// Mitsubishi GX Works2 project: MOD_SLAVE_v1   PLC: FX3G

// task Task_01 (event TRUE, interval 0, priority 31): POU_01

PROGRAM POU_01
VAR
  MODBUS_FB_SLAVE_1 : MODBUS_FB_SLAVE;
END_VAR
(* structured ladder/FBD written out as ST: instructions are called as NAME(EN, inputs, outputs); _pN, _eN, _tN stand for wires *)
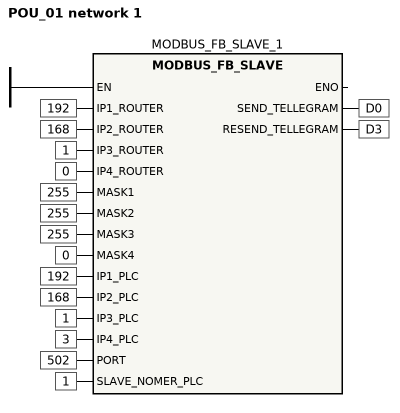
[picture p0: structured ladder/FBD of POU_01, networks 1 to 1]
(* network 1 *)
MODBUS_FB_SLAVE_1(EN := TRUE, IP1_ROUTER := 192, IP2_ROUTER := 168, IP3_ROUTER := 1, IP4_ROUTER := 0, MASK1 := 255, MASK2 := 255, MASK3 := 255, MASK4 := 0, IP1_PLC := 192, IP2_PLC := 168, IP3_PLC := 1, IP4_PLC := 3, PORT := 502, SLAVE_NOMER_PLC := 1, SEND_TELLEGRAM => D0, RESEND_TELLEGRAM => D3);
END_PROGRAM

FUNCTION_BLOCK MODBUS_FB_SLAVE
VAR_INPUT
  IP1_ROUTER : INT;
  IP2_ROUTER : INT;
  IP3_ROUTER : INT;
  IP4_ROUTER : INT;
  MASK1 : INT;
  MASK2 : INT;
  MASK3 : INT;
  MASK4 : INT;
  IP1_PLC : INT;
  IP2_PLC : INT;
  IP3_PLC : INT;
  IP4_PLC : INT;
  PORT : INT;
END_VAR
VAR_OUTPUT
  SEND_TELLEGRAM : INT;
  RESEND_TELLEGRAM : INT;
END_VAR
VAR_INPUT
  SLAVE_NOMER_PLC : INT;
END_VAR
(* structured ladder/FBD written out as ST: instructions are called as NAME(EN, inputs, outputs); _pN, _eN, _tN stand for wires *)
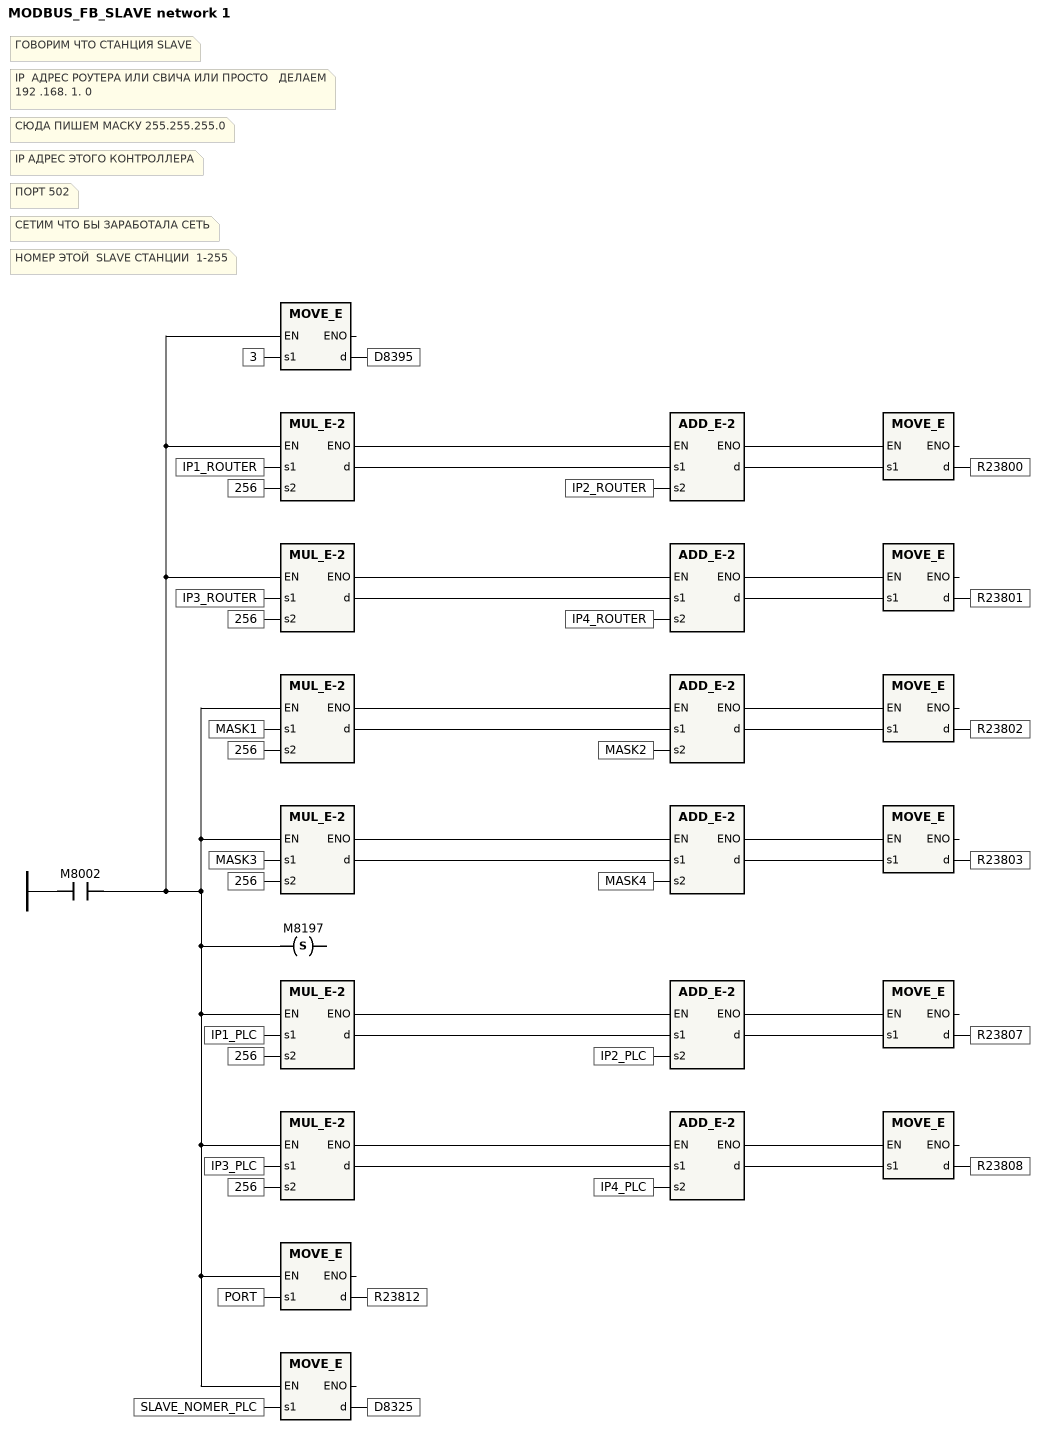
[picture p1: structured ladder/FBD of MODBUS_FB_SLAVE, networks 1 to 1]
(* network 1 *)
(* ГОВОРИМ ЧТО СТАНЦИЯ SLAVE *)
(* IP  АДРЕС РОУТЕРА ИЛИ СВИЧА ИЛИ ПРОСТО   ДЕЛАЕМ 192 .168. 1. 0 *)
(* СЮДА ПИШЕМ МАСКУ 255.255.255.0 *)
(* IP АДРЕС ЭТОГО КОНТРОЛЛЕРА *)
(* ПОРТ 502 *)
(* СЕТИМ ЧТО БЫ ЗАРАБОТАЛА СЕТЬ *)
(* НОМЕР ЭТОЙ  SLAVE СТАНЦИИ  1-255 *)
MOVE_E(M8002, 3, D8395);
_e2 := MUL_E(M8002, IP1_ROUTER, 256, _t1);
_e4 := ADD_E(_e2, _t1, IP2_ROUTER, _t3);
MOVE_E(_e4, _t3, R23800);
_e6 := MUL_E(M8002, IP3_ROUTER, 256, _t5);
_e8 := ADD_E(_e6, _t5, IP4_ROUTER, _t7);
MOVE_E(_e8, _t7, R23801);
_e10 := MUL_E(M8002, MASK1, 256, _t9);
_e12 := ADD_E(_e10, _t9, MASK2, _t11);
MOVE_E(_e12, _t11, R23802);
_e14 := MUL_E(M8002, MASK3, 256, _t13);
_e16 := ADD_E(_e14, _t13, MASK4, _t15);
MOVE_E(_e16, _t15, R23803);
_e18 := MUL_E(M8002, IP1_PLC, 256, _t17);
_e20 := ADD_E(_e18, _t17, IP2_PLC, _t19);
MOVE_E(_e20, _t19, R23807);
_e22 := MUL_E(M8002, IP3_PLC, 256, _t21);
_e24 := ADD_E(_e22, _t21, IP4_PLC, _t23);
MOVE_E(_e24, _t23, R23808);
MOVE_E(M8002, PORT, R23812);
SET(M8002, M8197);
MOVE_E(M8002, SLAVE_NOMER_PLC, D8325);
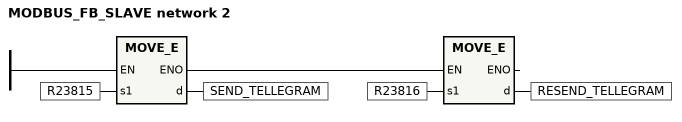
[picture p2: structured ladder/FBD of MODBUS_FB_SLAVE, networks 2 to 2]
(* network 2 *)
_e1 := MOVE_E(TRUE, R23815, SEND_TELLEGRAM);
MOVE_E(_e1, R23816, RESEND_TELLEGRAM);
END_FUNCTION_BLOCK
